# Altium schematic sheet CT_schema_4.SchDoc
size 284 x 211 mm
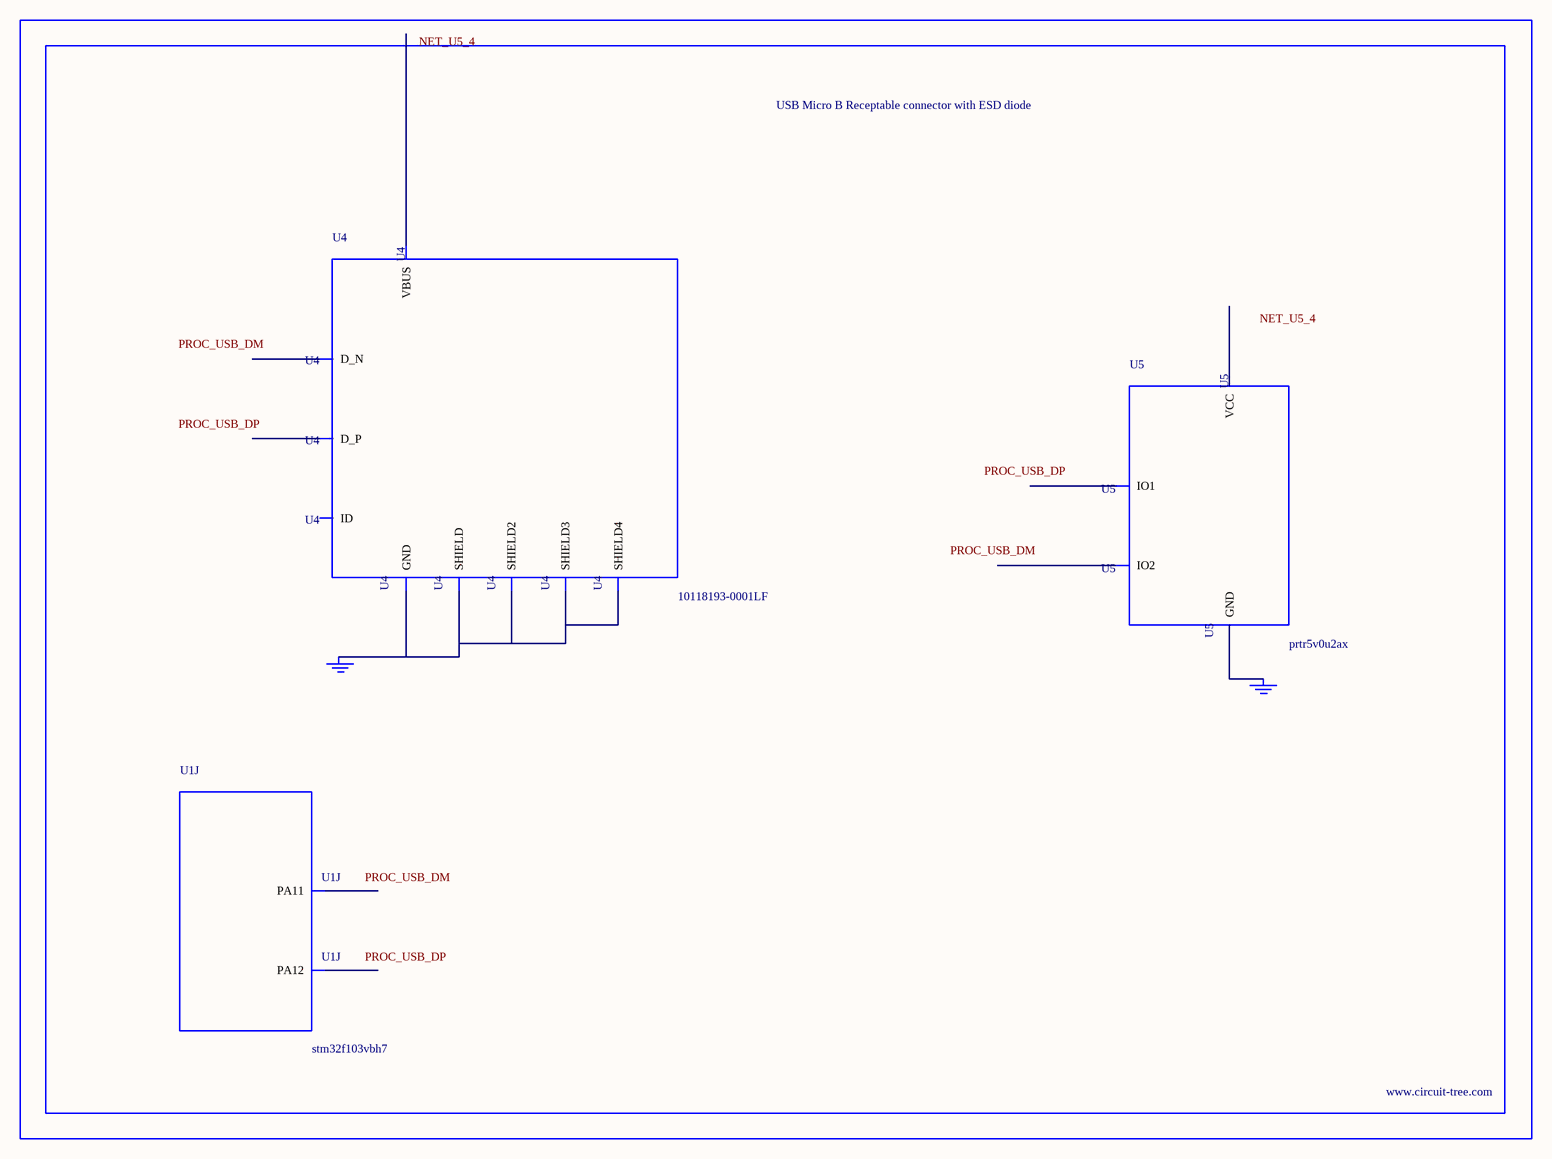
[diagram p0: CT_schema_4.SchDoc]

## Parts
BORDER3  (no value)
GND_INSTANCE_3_0  (no value)
GND_INSTANCE_3_1  (no value)
U1  stm32f103vbh7  [LFBGA100]  (part J of 10)
U4  10118193-0001LF  [FCI_10118193-0001LF]
U5  prtr5v0u2ax  [SOT143B]

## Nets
NetGND_INSTANCE_3_0_0: GND_INSTANCE_3_0.0(GND) U4.5(GND) U4.6(SHIELD) U4.7(SHIELD2) U4.8(SHIELD3) U4.9(SHIELD4)
NetGND_INSTANCE_3_1_0: GND_INSTANCE_3_1.0(GND) U5.1(GND)

Not connected (* = marked no-connect by the designer): U1 B10(PA12) C10(PA11); U4 1(VBUS) 2(D_N) 3(D_P) 4(ID); U5 2(IO1) 3(IO2) 4(VCC)

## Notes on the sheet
- Labels drawn without touching a wire or pin: NET_U5_4, PROC_USB_DM, PROC_USB_DP

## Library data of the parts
BORDER3 = BORDER_PAGE3
GND_INSTANCE_3_0 GND_INSTANCE_3_1 = GND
